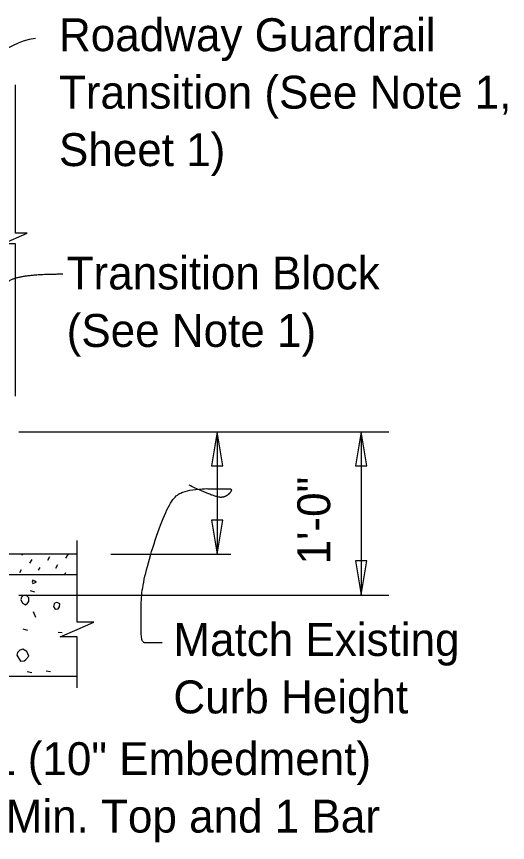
# Model space of a CAD drawing. Extents: x 21587 to 21656.3, y 56114 to 56157.2.
# Drawn here: x 21623.99 to 21626.99, y 56132.28 to 56137.34 of the extents above; entities that cross this region are included whole.
import ezdxf

# ---------------------------------------------------------------- set-up
doc = ezdxf.new("R2010")
doc.units = 0
for name, color, linetype in [('AdhocPoint_dp', 7, 'Continuous'), ('PlotBorder_dp', 7, 'Continuous'), ('SheetBorder_dp', 7, 'Continuous'), ('TextMisc', 7, 'Continuous')]:
    doc.layers.add(name, color=color, linetype=linetype)

msp = doc.modelspace()

# ---------------------------------------------------------------- linework, layer by layer
at = {"layer": 'AdhocPoint_dp'}
for p, q in [((21624.3563, 56134.0511), (21613.608, 56134.0511)), ((21622.1027, 56133.926), (21624.3563, 56133.926)), ((21624.3563, 56133.301), (21618.8279, 56133.301))]:
    msp.add_line(p, q, dxfattribs=at)
at = {"layer": 'PlotBorder_dp'}
for p, q in [((21623.9999, 56134.8009), (21626.2654, 56134.8009)), ((21625.2148, 56134.8009), (21625.2148, 56134.0509)), ((21626.0969, 56134.801), (21626.0969, 56133.801)), ((21624.5621, 56134.0509), (21625.2975, 56134.0509)), ((21623.9999, 56133.8009), (21626.2654, 56133.8009))]:
    msp.add_line(p, q, dxfattribs=at)
for points in [[(21623.978, 56135.0198), (21623.978, 56135.9514), (21623.9005, 56135.9514), (21624.0505, 56136.0177), (21623.978, 56136.0177), (21623.978, 56136.9265)], [(21624.3563, 56133.233), (21624.3563, 56133.5455), (21624.253, 56133.5455), (21624.3563, 56133.5905), (21624.4596, 56133.6355), (21624.3563, 56133.6355), (21624.3563, 56134.1353)]]:
    msp.add_lwpolyline(points, dxfattribs=at)
for points in [[(21625.2148, 56134.8009), (21625.1795, 56134.5927), (21625.2501, 56134.5927)], [(21626.0969, 56134.801), (21626.0616, 56134.5928), (21626.1322, 56134.5928)], [(21625.2148, 56134.0509), (21625.2501, 56134.2592), (21625.1795, 56134.2592)], [(21626.0969, 56133.801), (21626.1322, 56134.0093), (21626.0616, 56134.0093)]]:
    msp.add_lwpolyline(points, close=True, dxfattribs=at)
for points, degree in [([(21624.1009, 56137.2109), (21623.9928, 56137.1927), (21623.8601, 56137.1114), (21623.7028, 56136.9653), (21623.4907, 56136.7744)], 3), ([(21624.2687, 56135.7655), (21624.0532, 56135.7655), (21623.8906, 56135.7125), (21623.6609, 56135.412), (21623.4241, 56134.8039)], 2), ([(21624.8766, 56133.5082), (21624.7988, 56133.5082), (21624.7493, 56133.5082), (21624.7493, 56133.6284), (21624.7493, 56133.8724), (21624.919, 56134.3956), (21625.0533, 56134.4522), (21625.2547, 56134.4522), (21625.3148, 56134.4522), (21625.2688, 56134.3991), (21625.2017, 56134.3991), (21625.0427, 56134.4734)], 2)]:
    msp.add_open_spline(points, degree=degree, dxfattribs=at)
at = {"layer": 'TextMisc'}
for p, q in [((21624.0189, 56134.0456), (21624.022, 56134.0511)), ((21624.0677, 56133.9968), (21624.0807, 56134.0192)), ((21624.1771, 56134.0136), (21624.19, 56134.036)), ((21624.2877, 56134.0266), (21624.3007, 56134.049)), ((21624.0058, 56133.9392), (21624.0157, 56133.9563)), ((21624.1196, 56133.9533), (21624.1295, 56133.9704)), ((21624.2259, 56133.9648), (21624.2389, 56133.9872)), ((21624.1764, 56133.9243), (21624.1771, 56133.9254)), ((21624.2796, 56133.9243), (21624.2877, 56133.9383)), ((21624.0678, 56133.8276), (21624.0961, 56133.8206)), ((21624.1027, 56133.6624), (21624.0886, 56133.6978)), ((21624.0232, 56133.5932), (21624.0515, 56133.5862)), ((21624.2406, 56133.574), (21624.2653, 56133.5705)), ((21624.0513, 56133.3324), (21624.0796, 56133.3254)), ((21624.1663, 56133.3371), (21624.1928, 56133.3318))]:
    msp.add_line(p, q, dxfattribs=at)
for points in [[(21624.0858, 56133.8707), (21624.1052, 56133.8796), (21624.0982, 56133.8866), (21624.0858, 56133.8919), (21624.0805, 56133.8796), (21624.0858, 56133.8707)], [(21624.011, 56133.7727), (21624.0216, 56133.7515), (21624.0393, 56133.7409), (21624.0534, 56133.7515), (21624.0605, 56133.7621), (21624.0605, 56133.7833), (21624.0446, 56133.7993), (21624.0251, 56133.7975), (21624.0163, 56133.7886), (21624.011, 56133.7727)], [(21624.2123, 56133.7296), (21624.2211, 56133.7137), (21624.2406, 56133.7155), (21624.2494, 56133.7278), (21624.2512, 56133.7473), (21624.2388, 56133.7526), (21624.23, 56133.7543), (21624.2194, 56133.7508), (21624.2158, 56133.7473), (21624.2123, 56133.7296)], [(21623.9865, 56133.4326), (21624.0095, 56133.3955), (21624.0325, 56133.3972), (21624.0413, 56133.4061), (21624.0607, 56133.4255), (21624.0484, 56133.4556), (21624.0236, 56133.4697), (21624.0059, 56133.4627), (21623.9918, 56133.4485), (21623.9865, 56133.4326)]]:
    msp.add_lwpolyline(points, dxfattribs=at)

# ---------------------------------------------------------------- texts
at = {"layer": 'PlotBorder_dp'}
for s, p in [('Roadway Guardrail ', (21624.2454, 56137.1323)), ('Transition (See Note 1, ', (21624.2454, 56136.7803)), ('Sheet 1)', (21624.2454, 56136.4283)), ('Transition Block', (21624.2925, 56135.6728)), ('(See Note 1)', (21624.2925, 56135.3208)), ('Match Existing ', (21624.9463, 56133.4277)), ('Curb Height', (21624.9463, 56133.0757)), ('Dowel Bars 4L (10" Embedment) ', (21622.226, 56132.6977)), ('(Place 3 Bars Min. Top and 1 Bar ', (21622.226, 56132.3457))]:
    msp.add_text(s, height=0.2016, dxfattribs=at).set_placement(p)
at = {"layer": 'SheetBorder_dp'}
msp.add_text('1\'-0"', height=0.2016, rotation=90, dxfattribs=at).set_placement((21625.9073, 56133.9882))

doc.saveas('drawing.dxf')
